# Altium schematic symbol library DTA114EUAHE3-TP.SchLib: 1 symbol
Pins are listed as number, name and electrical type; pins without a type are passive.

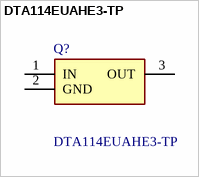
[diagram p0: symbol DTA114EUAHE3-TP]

## DTA114EUAHE3-TP
designator Q?
DIGITAL TRANSISTOR PNP 50V 0.1A SOT-323; Manufacturer_Name: MCC; Geometry.Height: 1.2mm
footprint SOT65P228X120-3N
pins: 1 IN, 2 GND, 3 OUT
